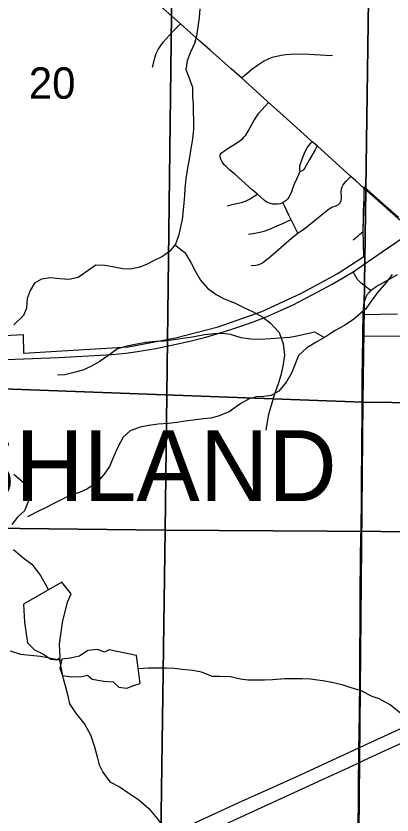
# Model space of a CAD drawing. Extents: x 0 to 34, y 0 to 22.
# Drawn here: x 14.618 to 15.12, y 15.656 to 16.722 of the extents above; entities that cross this region are included whole.
import ezdxf

# ---------------------------------------------------------------- set-up
doc = ezdxf.new("R2010")
doc.units = 0
for name, color, linetype in [('GM_X_City_Street', 7, 'Continuous'), ('GM_X_Corporation', 7, 'Continuous'), ('GM_X_Corporation_Text', 7, 'Continuous'), ('GM_X_Interstate_Route', 7, 'Continuous'), ('GM_X_Minor_Lake', 7, 'Continuous'), ('GM_X_Minor_River', 7, 'Continuous'), ('GM_X_Section', 7, 'Continuous'), ('GM_X_Section_Text', 7, 'Continuous'), ('GM_X_State_Route', 7, 'Continuous'), ('GM_X_Township_Road', 7, 'Continuous'), ('GM_X_US_Route', 7, 'Continuous')]:
    doc.layers.add(name, color=color, linetype=linetype)

msp = doc.modelspace()

# ---------------------------------------------------------------- linework, layer by layer
at = {"layer": 'GM_X_City_Street'}
for points in [[(14.7999, 16.654), (14.8006, 16.6571), (14.8029, 16.6661), (14.8049, 16.672), (14.8075, 16.6775), (14.8109, 16.6827), (14.8147, 16.6876), (14.8267, 16.701), (14.8357, 16.7105), (14.837, 16.7118)], [(14.9186, 16.6394), (14.9254, 16.6451), (14.9326, 16.6511), (14.9402, 16.6566), (14.9481, 16.6617), (14.9537, 16.6647), (14.9596, 16.667), (14.9656, 16.6687), (14.9718, 16.6699), (14.978, 16.6708), (14.9842, 16.6713), (14.9936, 16.6715), (15.0091, 16.671), (15.0308, 16.6698), (15.04, 16.6695)], [(14.9965, 16.5144), (14.9923, 16.5052), (14.989, 16.4976), (14.9869, 16.4918), (14.986, 16.4888), (14.985, 16.4859), (14.982, 16.4805), (14.9803, 16.4779), (14.9781, 16.4757), (14.9756, 16.4739), (14.9738, 16.473), (14.9728, 16.4725), (14.9697, 16.4715), (14.9666, 16.471), (14.9635, 16.4708), (14.9604, 16.4711), (14.9574, 16.4719), (14.9545, 16.4729), (14.9517, 16.4742), (14.9492, 16.476), (14.9399, 16.4844), (14.9353, 16.4884), (14.9329, 16.4902), (14.9098, 16.5109), (14.9028, 16.517), (14.8981, 16.5211), (14.8959, 16.5232), (14.894, 16.5257), (14.8923, 16.5283), (14.8909, 16.5311), (14.8901, 16.5341), (14.8903, 16.537), (14.8921, 16.5394), (14.8971, 16.5431), (14.8997, 16.5448), (14.9076, 16.5496), (14.9178, 16.5566), (14.9202, 16.5585), (14.9224, 16.5607), (14.9243, 16.5632), (14.9275, 16.5685), (14.9349, 16.582), (14.9381, 16.5873), (14.9417, 16.5924), (14.9457, 16.597), (14.95, 16.6016), (14.9548, 16.6068)], [(15.0126, 16.5548), (15.0087, 16.5498), (15.0068, 16.5473), (15.0052, 16.5447), (15.0024, 16.5391), (14.999, 16.5304), (14.9961, 16.5215), (14.9959, 16.5196), (14.9959, 16.5178), (14.9961, 16.5162), (14.9965, 16.5144)], [(15.0196, 16.5486), (15.0168, 16.5437), (15.0092, 16.5304), (15.0026, 16.5186), (15.0017, 16.5173), (15.0003, 16.516), (14.9988, 16.5152), (14.9965, 16.5144)], [(14.9938, 16.4322), (15.0011, 16.4373), (15.0061, 16.441), (15.0225, 16.4542), (15.0343, 16.464), (15.0368, 16.4656), (15.0393, 16.467), (15.0452, 16.4688), (15.0481, 16.4704), (15.0503, 16.4729), (15.0516, 16.4759), (15.052, 16.4791), (15.0518, 16.4884), (15.0522, 16.4913), (15.053, 16.494), (15.0543, 16.4966), (15.056, 16.4991), (15.0579, 16.5014), (15.06, 16.5035), (15.0648, 16.5081)], [(14.9001, 16.4688), (14.9063, 16.4703), (14.9187, 16.4733), (14.9247, 16.4753), (14.9276, 16.4766), (14.9304, 16.4781), (14.9357, 16.4816), (14.9399, 16.4844)], [(14.9938, 16.4322), (14.9906, 16.4386), (14.9849, 16.4501), (14.982, 16.4564), (14.9764, 16.4677), (14.9738, 16.473)], [(14.928, 16.431), (14.934, 16.432), (14.9431, 16.4335), (14.9491, 16.4351), (14.9549, 16.4372), (14.9661, 16.4421), (14.9745, 16.4458), (14.9801, 16.4481), (14.9849, 16.4501)], [(14.9316, 16.3892), (14.9376, 16.3895), (14.9406, 16.39), (14.9433, 16.3908), (14.9458, 16.3921), (14.9483, 16.3938), (14.9576, 16.4015), (14.9715, 16.4135), (14.9854, 16.4254), (14.9938, 16.4322)]]:
    msp.add_lwpolyline(points, dxfattribs=at)
at = {"layer": 'GM_X_Corporation'}
for points in [[(14.5699, 16.2941), (14.627, 16.2968), (14.6275, 16.2721), (14.7679, 16.2804), (14.8306, 16.2925), (14.8875, 16.3071), (14.9457, 16.3278), (14.9986, 16.352), (15.0464, 16.3781), (15.082, 16.4009), (15.081, 16.4369), (15.0815, 16.4513), (15.0817, 16.4625), (15.0822, 16.4781), (15.0822, 16.4894), (15.0823, 16.4941), (15.1114, 16.4681), (15.128, 16.4537)], [(15.1269, 16.3243), (15.0807, 16.3233), (15.0805, 16.3027), (15.0805, 16.2948), (15.2029, 16.2957)]]:
    msp.add_lwpolyline(points, dxfattribs=at)
at = {"layer": 'GM_X_Interstate_Route'}
for points in [[(14.5311, 15.496), (14.63, 15.5413), (14.7118, 15.579), (14.8389, 15.6372), (14.9152, 15.6722), (14.9916, 15.7068), (15.0397, 15.7287), (15.0754, 15.7454), (15.0875, 15.7511), (15.1751, 15.7912), (15.2317, 15.8169), (15.274, 15.8365), (15.3417, 15.8677), (15.4435, 15.9142), (15.4632, 15.9233), (15.5394, 15.9584), (15.5563, 15.9661), (15.6146, 15.9927)], [(15.0724, 15.724), (15.0751, 15.7253), (15.0804, 15.7278), (15.1114, 15.7422), (15.1708, 15.7691), (15.3911, 15.8702), (15.4477, 15.8961), (15.5325, 15.9347), (15.6256, 15.9776)], [(13.2404, 14.8287), (13.3346, 14.8775), (13.4174, 14.9203), (13.5638, 14.9957), (13.8537, 15.1453), (14.0112, 15.2265), (14.0636, 15.2536), (14.0682, 15.2561), (14.0856, 15.2652), (14.1412, 15.2931), (14.2109, 15.3274), (14.267, 15.3543), (14.4477, 15.4375), (14.5127, 15.4672), (14.5664, 15.4917), (14.8291, 15.6122), (14.8912, 15.6408), (14.9562, 15.6704), (15.0269, 15.7029), (15.0724, 15.724)]]:
    msp.add_lwpolyline(points, dxfattribs=at)
at = {"layer": 'GM_X_Minor_Lake'}
for points in [[(14.6276, 15.9372), (14.6291, 15.9129), (14.6306, 15.9007), (14.6328, 15.8855), (14.6423, 15.876), (14.6533, 15.8706), (14.6643, 15.8638), (14.6722, 15.8626), (14.6764, 15.866), (14.6757, 15.8835), (14.6796, 15.9127), (14.6865, 15.9397), (14.6911, 15.9507), (14.6786, 15.9663)], [(14.6786, 15.9663), (14.6276, 15.9372)], [(14.7786, 15.8685), (14.7418, 15.8759), (14.7357, 15.8729), (14.7266, 15.8764), (14.7134, 15.8753), (14.7023, 15.8677), (14.6898, 15.8651), (14.6788, 15.8636), (14.6761, 15.8515), (14.6798, 15.842), (14.6923, 15.84), (14.7053, 15.8407), (14.7129, 15.8422), (14.7193, 15.8369), (14.7348, 15.8341), (14.7474, 15.8333), (14.7549, 15.8264), (14.7656, 15.8249), (14.7747, 15.8286), (14.7834, 15.8313)], [(14.7834, 15.8313), (14.7786, 15.8685)]]:
    msp.add_lwpolyline(points, dxfattribs=at)
at = {"layer": 'GM_X_Minor_River'}
for points in [[(14.8628, 16.7318), (14.862, 16.72), (14.8605, 16.7075), (14.8585, 16.6957), (14.8558, 16.6855), (14.8501, 16.6729), (14.8459, 16.6623), (14.8443, 16.6505), (14.8485, 16.6403), (14.853, 16.6269), (14.8533, 16.6144), (14.8541, 16.6045), (14.854, 16.5943), (14.8544, 16.5821), (14.8544, 16.5715), (14.8532, 16.5578), (14.8512, 16.5452), (14.8489, 16.5312), (14.8466, 16.5194), (14.8443, 16.5046), (14.8431, 16.4921), (14.8427, 16.4822), (14.8411, 16.4677), (14.8392, 16.4503), (14.8369, 16.4385), (14.8346, 16.4286), (14.8304, 16.4176), (14.8231, 16.4081)], [(14.8297, 16.4168), (14.8429, 16.4066), (14.8508, 16.3929), (14.8572, 16.381), (14.864, 16.3696), (14.8731, 16.359), (14.8849, 16.3502), (14.8955, 16.3448), (14.9095, 16.3391), (14.9228, 16.3326), (14.9334, 16.3276), (14.9471, 16.3203), (14.9573, 16.3123), (14.9691, 16.2997), (14.9743, 16.2845), (14.9762, 16.2693), (14.9739, 16.2549), (14.9712, 16.2427), (14.9681, 16.2325), (14.9628, 16.2173), (14.9589, 16.2055), (14.9547, 16.1903), (14.9528, 16.1804), (14.9512, 16.1694)], [(14.8231, 16.4081), (14.8132, 16.4013), (14.8022, 16.3957), (14.7927, 16.3908), (14.7828, 16.387), (14.7706, 16.3844), (14.76, 16.3848), (14.7463, 16.3871), (14.7364, 16.3891), (14.7243, 16.3895), (14.714, 16.3823), (14.7007, 16.3732), (14.6881, 16.3702), (14.6764, 16.3714), (14.6638, 16.3726), (14.6517, 16.3707), (14.6422, 16.3655), (14.6364, 16.3556), (14.6326, 16.345), (14.6314, 16.3321), (14.6276, 16.3222), (14.6146, 16.3101)], [(15.1199, 16.3769), (15.1122, 16.3667), (15.1, 16.3531), (15.0916, 16.3413), (15.0844, 16.3311), (15.0684, 16.3175), (15.0562, 16.3092), (15.0429, 16.3017), (15.033, 16.2952), (15.0182, 16.2869), (15.006, 16.2794), (14.9946, 16.2688), (14.99, 16.2563), (14.9854, 16.2453), (14.9789, 16.2339), (14.9686, 16.2214), (14.9583, 16.2158), (14.9484, 16.2143), (14.9389, 16.2136), (14.9287, 16.211), (14.9177, 16.2049), (14.902, 16.194), (14.8876, 16.188), (14.8777, 16.1854), (14.8678, 16.1843), (14.8435, 16.1813), (14.8321, 16.1795), (14.8211, 16.1784), (14.8074, 16.1773), (14.7949, 16.1755), (14.7835, 16.1732)], [(15.0288, 16.2929), (15.0163, 16.3003), (15.0061, 16.298), (14.9947, 16.2954), (14.9833, 16.2932), (14.9692, 16.2921), (14.9574, 16.2914), (14.9434, 16.2903), (14.9312, 16.2908), (14.918, 16.2927), (14.9039, 16.297), (14.8933, 16.2985), (14.8815, 16.2978), (14.8694, 16.2967), (14.8534, 16.2934), (14.8401, 16.2915), (14.8287, 16.2897), (14.8154, 16.2882), (14.8044, 16.2875), (14.7908, 16.2864), (14.7809, 16.2846), (14.7657, 16.2816), (14.7531, 16.2779), (14.7429, 16.2703), (14.7284, 16.2605), (14.7174, 16.2545), (14.7067, 16.2492), (14.6972, 16.2466), (14.6828, 16.2432), (14.6729, 16.2425)], [(14.7835, 16.1732), (14.7702, 16.1684), (14.7607, 16.16), (14.7534, 16.1464), (14.7481, 16.1346), (14.7423, 16.121), (14.7351, 16.1104), (14.7255, 16.0994), (14.713, 16.0911), (14.7031, 16.0866), (14.6875, 16.081), (14.6772, 16.0757), (14.6674, 16.0712), (14.6578, 16.0663), (14.6476, 16.0614), (14.6331, 16.0538)], [(14.6145, 16.1106), (14.627, 16.0999), (14.6326, 16.0877), (14.6341, 16.0752), (14.6291, 16.0615), (14.6196, 16.0532), (14.612, 16.0433)], [(14.6142, 16.0102), (14.6267, 15.9992), (14.6388, 15.9904), (14.6502, 15.9755), (14.6608, 15.9562)], [(14.6097, 15.8746), (14.6234, 15.8704), (14.637, 15.8688), (14.6503, 15.8676), (14.6785, 15.8625)], [(14.6753, 15.8651), (14.6798, 15.8409), (14.6835, 15.8268), (14.6869, 15.8147), (14.6892, 15.804), (14.6971, 15.7922), (14.7096, 15.7766), (14.7172, 15.7625), (14.7224, 15.7465), (14.7258, 15.7332), (14.7288, 15.7225), (14.7337, 15.713), (14.7428, 15.7001), (14.7565, 15.6928), (14.7667, 15.6859), (14.7815, 15.676), (14.7951, 15.6642), (14.8061, 15.6512), (14.8156, 15.6386)], [(15.1314, 15.7913), (15.117, 15.8028), (15.1026, 15.8105), (15.0932, 15.8139), (15.0784, 15.8212), (15.0651, 15.8254), (15.0545, 15.8289), (15.0416, 15.832), (15.0298, 15.8343), (15.0109, 15.8371), (14.9995, 15.8375), (14.9885, 15.8376), (14.9763, 15.8372), (14.96, 15.8362), (14.9494, 15.8358), (14.9395, 15.8355), (14.927, 15.8356), (14.9171, 15.8371), (14.9038, 15.8402), (14.8894, 15.8407), (14.8799, 15.8407), (14.8651, 15.8461), (14.8537, 15.8484), (14.8393, 15.85), (14.8294, 15.8512), (14.8184, 15.8516), (14.7945, 15.8517), (14.7809, 15.8507)]]:
    msp.add_lwpolyline(points, dxfattribs=at)
at = {"layer": 'GM_X_Section'}
for points in [[(14.0875, 17.2264), (15.0949, 17.2175), (15.0807, 16.2067), (14.0733, 16.244)], [(15.0949, 17.2175), (16.1, 17.2094), (16.0877, 16.1952), (15.0807, 16.2067)], [(13.8241, 17.0583), (14.8292, 17.0502), (14.8169, 16.036), (13.8099, 16.0475)], [(14.8292, 17.0502), (15.652, 17.0394), (15.8392, 17.0281), (15.825, 16.0298), (14.8169, 16.036)], [(14.0733, 16.244), (15.0807, 16.2067), (15.0711, 15.2009), (14.0694, 15.2136)], [(15.0807, 16.2067), (16.0877, 16.1952), (16.0735, 15.1863), (15.0711, 15.2009)], [(13.8099, 16.0475), (14.8169, 16.036), (14.8027, 15.0271), (13.8003, 15.0417)], [(14.8169, 16.036), (15.825, 16.0298), (15.8146, 15.0251), (14.8027, 15.0271)]]:
    msp.add_lwpolyline(points, close=True, dxfattribs=at)
at = {"layer": 'GM_X_State_Route'}
for p, q in [((15.0196, 16.5486), (15.0126, 16.5548)), ((15.0648, 16.5081), (15.0196, 16.5486))]:
    msp.add_line(p, q, dxfattribs=at)
for points in [[(14.837, 16.7118), (14.8142, 16.732), (14.7983, 16.7469), (14.7671, 16.7772), (14.7632, 16.781)], [(14.9186, 16.6394), (14.905, 16.6517), (14.877, 16.6763), (14.8631, 16.6887), (14.837, 16.7118)], [(14.9548, 16.6068), (14.9534, 16.6081), (14.9234, 16.6351), (14.9186, 16.6394)], [(15.0126, 16.5548), (15.0064, 16.5603), (14.9742, 16.5895), (14.9548, 16.6068)], [(15.0825, 16.4919), (15.0713, 16.5023), (15.0648, 16.5081)], [(15.1131, 16.4646), (15.1116, 16.4659), (15.0825, 16.4919)], [(15.1482, 16.4335), (15.1468, 16.4349), (15.1423, 16.4391), (15.1282, 16.4515), (15.1131, 16.4646)], [(15.0912, 16.3556), (15.088, 16.3579), (15.0785, 16.3656), (15.0763, 16.3677), (15.0737, 16.3706), (15.0675, 16.3805)], [(15.0912, 16.3556), (15.0935, 16.3575), (15.0986, 16.3611), (15.1123, 16.3688), (15.1269, 16.3773)], [(15.081, 16.3211), (15.0811, 16.3268), (15.0819, 16.336), (15.0824, 16.339), (15.0832, 16.3421), (15.0842, 16.3451), (15.0855, 16.348), (15.087, 16.3507), (15.0889, 16.3532), (15.0912, 16.3556)], [(15.0807, 16.2926), (15.0807, 16.3005), (15.081, 16.3211)], [(15.0786, 16.0743), (15.0788, 16.0973), (15.0796, 16.1968), (15.0799, 16.237), (15.0807, 16.2926)], [(15.0765, 15.8744), (15.0769, 15.9109), (15.0772, 15.945), (15.0777, 16.004), (15.0782, 16.0413), (15.0786, 16.0743)], [(15.075, 15.7073), (15.0751, 15.7253), (15.0752, 15.7306), (15.0754, 15.7454), (15.0756, 15.7617), (15.0762, 15.7958), (15.0765, 15.8331), (15.0765, 15.8704), (15.0765, 15.8744)], [(15.0746, 15.6675), (15.0749, 15.6932), (15.075, 15.7073)], [(15.069, 15.2033), (15.069, 15.2115), (15.0691, 15.2395), (15.0697, 15.2923), (15.0706, 15.3389), (15.071, 15.3731), (15.0717, 15.4117), (15.072, 15.4364), (15.0723, 15.4645), (15.0724, 15.4826), (15.073, 15.508), (15.0731, 15.5472), (15.0734, 15.5782), (15.0738, 15.6124), (15.0744, 15.6497), (15.0746, 15.6675)]]:
    msp.add_lwpolyline(points, dxfattribs=at)
at = {"layer": 'GM_X_Township_Road'}
for points in [[(15.0805, 16.4342), (15.0812, 16.4347), (15.0817, 16.4491), (15.0819, 16.4603), (15.0824, 16.4759), (15.0824, 16.4872), (15.0825, 16.4919)], [(15.0678, 16.4234), (15.0743, 16.4289), (15.0765, 16.4308), (15.0805, 16.4342)]]:
    msp.add_lwpolyline(points, dxfattribs=at)
at = {"layer": 'GM_X_US_Route'}
for points in [[(15.0675, 16.3805), (15.1063, 16.4073), (15.1468, 16.4349)], [(14.5815, 16.2629), (14.6742, 16.2661), (14.7145, 16.2684), (14.7456, 16.2704), (14.7641, 16.2723), (14.7796, 16.2744), (14.8041, 16.2785), (14.8316, 16.2839), (14.8498, 16.288), (14.8709, 16.2936), (14.8948, 16.3005), (14.9126, 16.3062), (14.9331, 16.3135), (14.9505, 16.3203), (14.9705, 16.3289), (14.9874, 16.3368), (15.0206, 16.3538), (15.0398, 16.3641), (15.0675, 16.3805)]]:
    msp.add_lwpolyline(points, dxfattribs=at)

# ---------------------------------------------------------------- texts
at = {"layer": 'GM_X_Corporation_Text'}
msp.add_text('ASHLAND', height=0.0947, rotation=0, dxfattribs=at).set_placement((14.4476, 16.0746))
at = {"layer": 'GM_X_Section_Text'}
msp.add_text('20', height=0.04186, rotation=0, dxfattribs=at).set_placement((14.6347, 16.6117))

doc.saveas('drawing.dxf')
